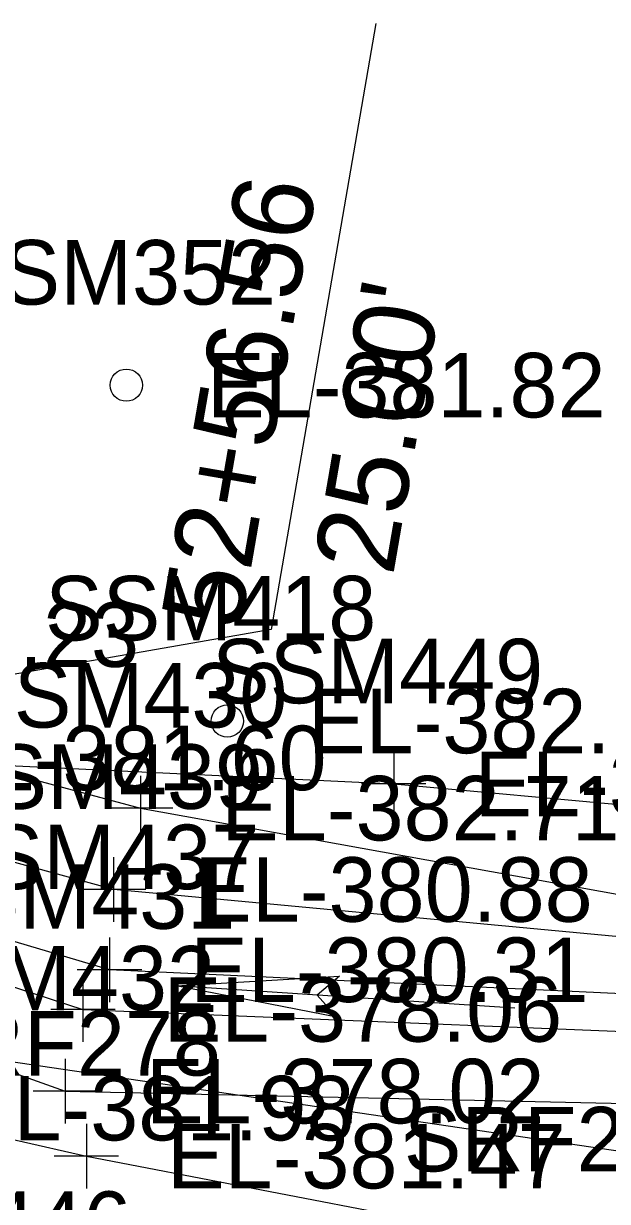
# Model space of a CAD drawing. Extents: x 1189978 to 1314812, y 571533 to 629339.
# Drawn here: x 1217562.1 to 1217598.3, y 620970.5 to 621043.5 of the extents above; entities that cross this region are included whole.
import ezdxf

# ---------------------------------------------------------------- set-up
doc = ezdxf.new("R2010")
doc.units = 0
for name, color, linetype in [('SURVEY - DRAINAGE - Bridge Hydraulic Data with Text', 7, 'Continuous'), ('SURVEY - DTM - Breaklines', 7, 'Continuous'), ('SURVEY - DTM - Breaklines - Points - Elevations', 7, 'Continuous'), ('SURVEY - DTM - Breaklines - Points - Locators', 7, 'Continuous'), ('SURVEY - DTM - Breaklines - Points - Numbers', 7, 'Continuous'), ('SURVEY - DTM - Spot Points - Elevations', 7, 'Continuous'), ('SURVEY - DTM - Spot Points - Locators', 7, 'Continuous'), ('SURVEY - DTM - Spot Points - Point Numbers', 7, 'Continuous'), ('SURVEY - PROPERTY - Property Lines', 7, 'Continuous'), ('SURVEY - PROPERTY - Station and Offset Flags', 7, 'Continuous'), ('SURVEY - VEGETATION - Features - Points - Elevations', 7, 'Continuous'), ('SURVEY - VEGETATION - Features - Points - Locators', 7, 'Continuous'), ('SURVEY - VEGETATION - Features - Points - Numbers', 7, 'Continuous'), ('SURVEY - VEGETATION - Features with Text', 7, 'Continuous')]:
    doc.layers.add(name, color=color, linetype=linetype)

msp = doc.modelspace()

# ---------------------------------------------------------------- linework, layer by layer
at = {"layer": 'SURVEY - DRAINAGE - Bridge Hydraulic Data with Text'}
msp.add_line((1217592.523, 620982.473), (1217571.559, 620983.857), dxfattribs=at)
msp.add_lwpolyline([(1217571.559, 620983.857), (1217581.669, 620984.443), (1217580.29, 620983.281), (1217581.501, 620981.898)], close=True, dxfattribs=at)
msp.add_lwpolyline([(1217571.559, 620983.857), (1217581.669, 620984.443), (1217580.29, 620983.281), (1217581.501, 620981.898), (1217571.559, 620983.857)], dxfattribs=at)
at = {"layer": 'SURVEY - DTM - Breaklines'}
for points in [[(1217505.41, 621014.241), (1217516.986, 621012.366), (1217518.094, 621005.103), (1217531.462, 621005.047), (1217569.338, 620994.867), (1217611.558, 620987.234)], [(1217508.488, 621010.319), (1217511.862, 621009.77), (1217513.632, 621003.754), (1217524.945, 620995.725), (1217565.777, 620982.387), (1217612.455, 620980.49)], [(1217611.949, 620982.746), (1217567.417, 620984.846), (1217526.977, 620996.852), (1217516.068, 621003.42), (1217514.47, 621008.391), (1217511.862, 621009.77)], [(1217611.37, 620985.73), (1217567.667, 620989.823), (1217529.708, 621000.214), (1217516.95, 621003.562)], [(1217509.634, 621001.298), (1217509.945, 621001.867), (1217523.3, 620992.1), (1217564.682, 620977.322), (1217612.571, 620976.268)], [(1217488.011, 620930.211), (1217495.393, 620955.978), (1217498.704, 620982.052), (1217509.421, 620998.087), (1217530.897, 620979.928), (1217552.905, 620976.266), (1217565.985, 620973.288), (1217596.907, 620967.343), (1217617.462, 620968.299)]]:
    msp.add_lwpolyline(points, dxfattribs=at)
at = {"layer": 'SURVEY - DTM - Breaklines - Points - Locators'}
for p, q in [((1217569.338, 620996.867), (1217569.338, 620992.867)), ((1217571.338, 620994.867), (1217567.338, 620994.867)), ((1217567.667, 620991.823), (1217567.667, 620987.823)), ((1217569.667, 620989.823), (1217565.667, 620989.823)), ((1217567.417, 620986.846), (1217567.417, 620982.846)), ((1217569.417, 620984.846), (1217565.417, 620984.846)), ((1217565.777, 620984.387), (1217565.777, 620980.387)), ((1217567.777, 620982.387), (1217563.777, 620982.387)), ((1217564.682, 620979.322), (1217564.682, 620975.322)), ((1217566.682, 620977.322), (1217562.682, 620977.322)), ((1217565.985, 620975.288), (1217565.985, 620971.288)), ((1217567.985, 620973.288), (1217563.985, 620973.288))]:
    msp.add_line(p, q, dxfattribs=at)
at = {"layer": 'SURVEY - DTM - Spot Points - Locators'}
for centre in [(1217568.464, 621021.097), (1217574.717, 621000.271)]:
    msp.add_circle(centre, 1, dxfattribs=at)
at = {"layer": 'SURVEY - PROPERTY - Property Lines'}
msp.add_line((1217486.833, 620990.132), (1218812.312, 620794.767), dxfattribs=at)
at = {"layer": 'SURVEY - PROPERTY - Station and Offset Flags'}
msp.add_line((1217583.918, 621043.521), (1217577.436, 621005.94), dxfattribs=at)
msp.add_lwpolyline([(1217577.436, 621005.94), (1217486.833, 620990.132)], dxfattribs=at)
at = {"layer": 'SURVEY - VEGETATION - Features - Points - Locators'}
for p, q in [((1217585.026, 620998.37), (1217585.026, 620994.37)), ((1217587.026, 620996.37), (1217583.026, 620996.37))]:
    msp.add_line(p, q, dxfattribs=at)
at = {"layer": 'SURVEY - VEGETATION - Features with Text'}
msp.add_lwpolyline([(1217602.668, 620954.843), (1217559.599, 620962.102), (1217546.125, 620967.761), (1217551.182, 620997.982), (1217585.026, 620996.37), (1217615.636, 620993.572)], dxfattribs=at)

# ---------------------------------------------------------------- texts
at = {"layer": 'SURVEY - DTM - Breaklines - Points - Elevations'}
for s, p in [('EL-382.71', (1217574.338, 620992.867)), ('EL-380.88', (1217572.667, 620987.823)), ('EL-380.31', (1217572.417, 620982.846)), ('EL-378.06', (1217570.777, 620980.387)), ('EL-378.02', (1217569.682, 620975.322)), ('EL-381.98', (1217557.905, 620974.266)), ('EL-381.47', (1217570.985, 620971.288))]:
    msp.add_text(s, height=4, dxfattribs=at).set_placement(p)
at = {"layer": 'SURVEY - DTM - Breaklines - Points - Numbers'}
for s, p in [('SSM430', (1217557.925, 620999.867)), ('SSM439', (1217556.412, 620994.823)), ('SSM437', (1217556.177, 620989.846)), ('SSM431', (1217554.695, 620987.387)), ('SSM432', (1217553.442, 620982.322)), ('SRF278', (1217554.698, 620978.288)), ('SRF279', (1217585.652, 620972.343))]:
    msp.add_text(s, height=4, dxfattribs=at).set_placement(p)
at = {"layer": 'SURVEY - DTM - Spot Points - Elevations'}
for s, p in [('EL-381.82', (1217573.464, 621019.097)), ('EL-382.23', (1217544.566, 621003.628)), ('EL-382.12', (1217579.717, 620998.271))]:
    msp.add_text(s, height=4, dxfattribs=at).set_placement(p)
at = {"layer": 'SURVEY - DTM - Spot Points - Point Numbers'}
for s, p in [('SSM352', (1217557.224, 621026.097)), ('SSM418', (1217563.43, 621005.271))]:
    msp.add_text(s, height=4, dxfattribs=at).set_placement(p)
at = {"layer": 'SURVEY - PROPERTY - Station and Offset Flags'}
for s, p in [('52+56.56', (1217575.515, 621005.833)), ("25.00'", (1217584.977, 621009.212))]:
    msp.add_text(s, height=5, rotation=80.21411, dxfattribs=at).set_placement(p)
at = {"layer": 'SURVEY - VEGETATION - Features - Points - Elevations'}
for s, p in [('EL-381.60', (1217556.182, 620995.982)), ('EL-382.41', (1217590.026, 620994.37))]:
    msp.add_text(s, height=4, dxfattribs=at).set_placement(p)
at = {"layer": 'SURVEY - VEGETATION - Features - Points - Numbers'}
for s, p in [('SSM449', (1217573.771, 621001.37)), ('SSM446', (1217548.249, 620967.102))]:
    msp.add_text(s, height=4, dxfattribs=at).set_placement(p)

doc.saveas('drawing.dxf')
